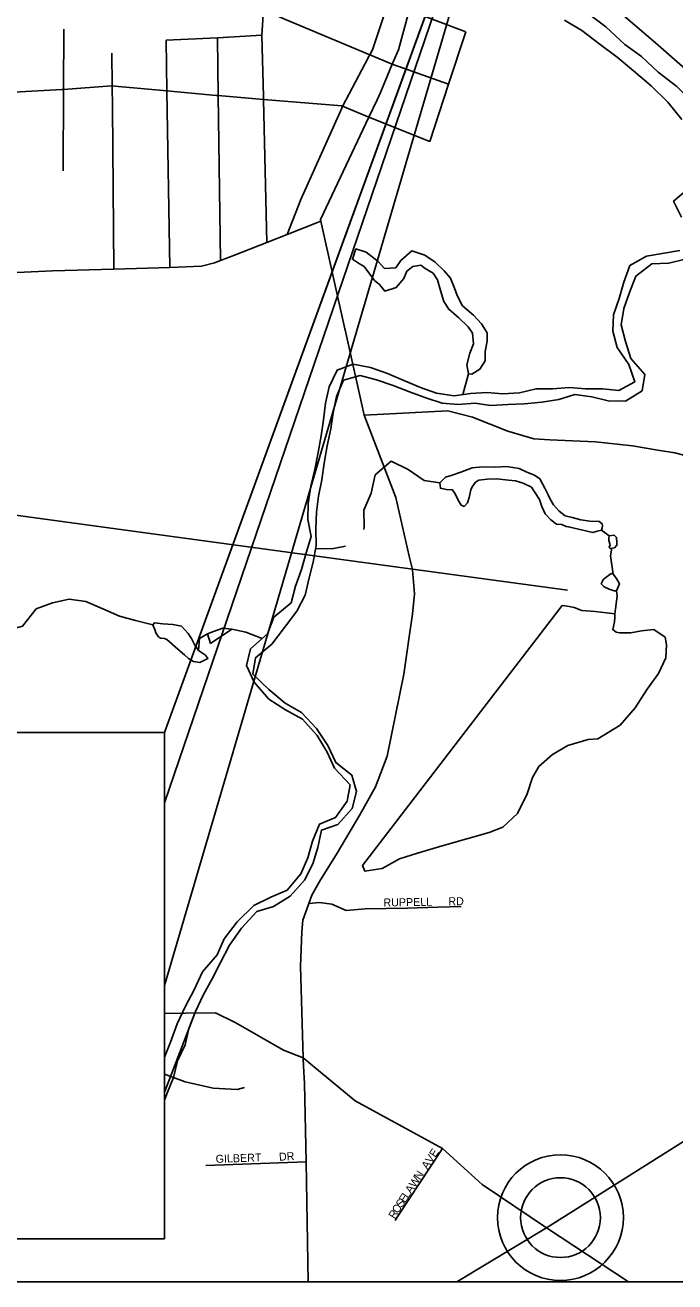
# Model space of a CAD drawing. Extents: x -37878.7 to -37844.7, y -19791.4 to -19769.4.
# Drawn here: x -37873.196 to -37872.428, y -19777.385 to -19775.898 of the extents above; entities that cross this region are included whole.
import ezdxf

# ---------------------------------------------------------------- set-up
doc = ezdxf.new("R2010")
doc.units = 0
for name, color, linetype in [('Default', 7, 'Continuous'), ('GM_X_City_Street', 7, 'Continuous'), ('GM_X_County_Road', 7, 'Continuous'), ('GM_X_Major_River', 7, 'Continuous'), ('GM_X_Minor_Lake', 7, 'Continuous'), ('GM_X_Minor_River', 7, 'Continuous'), ('GM_X_Rail_Line', 7, 'Continuous'), ('GM_X_State_Route', 7, 'Continuous'), ('GM_X_Township_Subdivision', 7, 'Continuous'), ('GM_X_Township_Subdivision_Text', 7, 'Continuous'), ('GM_X_Unincorporated', 7, 'Continuous'), ('SH_Data', 7, 'Continuous'), ('TX_P_1', 7, 'Continuous')]:
    doc.layers.add(name, color=color, linetype=linetype)

msp = doc.modelspace()

# ---------------------------------------------------------------- linework, layer by layer
at = {"layer": 'Default'}
msp.add_line((-37872.5631, -19777.3094), (-37872.5631, -19777.3094), dxfattribs=at)
msp.add_lwpolyline([(-37873.0316, -19777.1396), (-37873.0072, -19777.1485), (-37872.9741, -19777.156), (-37872.9456, -19777.1576), (-37872.9369, -19777.1555)], dxfattribs=at)
at = {"layer": 'GM_X_City_Street'}
for points in [[(-37872.9146, -19775.9827), (-37872.9163, -19775.9098), (-37872.9145, -19775.8801), (-37872.9178, -19775.8408)], [(-37872.9145, -19775.8801), (-37872.8882, -19775.8912), (-37872.7887, -19775.9332), (-37872.7621, -19775.9444)], [(-37872.7907, -19775.9368), (-37872.7905, -19775.9365), (-37872.7887, -19775.9332), (-37872.7856, -19775.9272), (-37872.7678, -19775.8739)], [(-37872.7419, -19775.8807), (-37872.6749, -19775.9059)], [(-37873.1514, -19776.0706), (-37873.1509, -19775.9741), (-37873.1506, -19775.9028)], [(-37873.0295, -19775.916), (-37872.9689, -19775.9129), (-37872.9163, -19775.9098)], [(-37872.7177, -19776.0358), (-37872.6954, -19775.9679), (-37872.6749, -19775.9059)], [(-37873.0253, -19776.1847), (-37873.0286, -19775.9759), (-37873.0295, -19775.916)], [(-37872.9652, -19776.1767), (-37872.968, -19775.9815), (-37872.9689, -19775.9129)], [(-37873.0932, -19775.9952), (-37873.0932, -19775.9952), (-37873.0934, -19775.9698), (-37873.0937, -19775.9314)], [(-37872.8219, -19775.9962), (-37872.8218, -19775.996), (-37872.8208, -19775.9939), (-37872.8206, -19775.9934), (-37872.7907, -19775.9368)], [(-37872.7621, -19775.9444), (-37872.6954, -19775.9679)], [(-37873.5126, -19775.9884), (-37873.5125, -19775.9884), (-37873.4035, -19775.9852), (-37873.35, -19775.9836), (-37873.2955, -19775.982), (-37873.1528, -19775.9743), (-37873.1509, -19775.9741), (-37873.0942, -19775.9697), (-37873.0934, -19775.9698), (-37873.0862, -19775.9705), (-37873.086, -19775.9705)], [(-37873.086, -19775.9705), (-37873.0286, -19775.9759), (-37872.9705, -19775.9813), (-37872.968, -19775.9815), (-37872.9145, -19775.9859), (-37872.8217, -19775.9935), (-37872.8208, -19775.9939), (-37872.7898, -19776.0068)], [(-37872.9106, -19776.1552), (-37872.9145, -19775.9859), (-37872.9146, -19775.9828), (-37872.9146, -19775.9827)], [(-37873.0916, -19776.1867), (-37873.0932, -19775.9952)], [(-37872.8864, -19776.1457), (-37872.8702, -19776.1043), (-37872.8219, -19775.9962)], [(-37872.7898, -19776.0068), (-37872.7177, -19776.0358)], [(-37873.2057, -19776.1908), (-37873.1641, -19776.1888), (-37873.0916, -19776.1867), (-37873.0645, -19776.1859), (-37873.0253, -19776.1847), (-37872.9879, -19776.1835), (-37872.9722, -19776.1795), (-37872.9652, -19776.1767), (-37872.9487, -19776.1701), (-37872.9106, -19776.1552), (-37872.8864, -19776.1457), (-37872.8466, -19776.1301)], [(-37872.7954, -19776.3597), (-37872.6965, -19776.3546), (-37872.667, -19776.3622), (-37872.6255, -19776.3785), (-37872.5948, -19776.3876), (-37872.5758, -19776.3887), (-37872.5218, -19776.3912), (-37872.478, -19776.396), (-37872.448, -19776.401), (-37872.4479, -19776.401)], [(-37872.4479, -19776.401), (-37872.4277, -19776.4043), (-37872.3836, -19776.4156), (-37872.3413, -19776.4212), (-37872.2895, -19776.4275), (-37872.2126, -19776.4447), (-37872.1816, -19776.4523), (-37872.1611, -19776.4625), (-37872.1401, -19776.4772), (-37872.122, -19776.4944), (-37872.1061, -19776.518)]]:
    msp.add_lwpolyline(points, dxfattribs=at)
at = {"layer": 'GM_X_County_Road'}
for points in [[(-37872.6858, -19777.3854), (-37872.5796, -19777.3214), (-37872.0827, -19777.0084)], [(-37872.8675, -19777.1204), (-37872.8909, -19777.111), (-37872.9471, -19777.079), (-37872.9713, -19777.0671), (-37873.0065, -19777.0675), (-37873.0316, -19777.0677)], [(-37872.4825, -19777.3854), (-37872.5796, -19777.3214), (-37872.6559, -19777.2703), (-37872.7025, -19777.2277), (-37872.8058, -19777.171), (-37872.8675, -19777.1204)]]:
    msp.add_lwpolyline(points, dxfattribs=at)
at = {"layer": 'GM_X_Major_River'}
msp.add_line((-37873.0316, -19777.1609), (-37872.9949, -19777.0654), dxfattribs=at)
for points in [[(-37872.4195, -19776.0097), (-37872.4362, -19775.9892), (-37872.4559, -19775.9699), (-37872.4768, -19775.9521), (-37872.496, -19775.9358), (-37872.5176, -19775.9196), (-37872.538, -19775.9045), (-37872.5583, -19775.892)], [(-37872.5285, -19775.886), (-37872.5093, -19775.9001), (-37872.4869, -19775.9208), (-37872.4673, -19775.9352), (-37872.4476, -19775.9538), (-37872.4256, -19775.9708), (-37872.4062, -19775.9905), (-37872.3865, -19776.0098), (-37872.3668, -19776.0287), (-37872.3475, -19776.0469), (-37872.3271, -19776.0597), (-37872.3068, -19776.0741), (-37872.2852, -19776.0888), (-37872.266, -19776.1017), (-37872.2465, -19776.113), (-37872.2254, -19776.1251), (-37872.2062, -19776.1369), (-37872.1839, -19776.15), (-37872.165, -19776.169), (-37872.1449, -19776.186), (-37872.1246, -19776.1989), (-37872.105, -19776.2102), (-37872.0832, -19776.2208)], [(-37872.4201, -19776.1255), (-37872.4292, -19776.1063), (-37872.4095, -19776.09)], [(-37872.4156, -19776.1751), (-37872.4349, -19776.1797), (-37872.4549, -19776.1805), (-37872.4739, -19776.1953), (-37872.4815, -19776.2145), (-37872.4883, -19776.2336), (-37872.4913, -19776.2526), (-37872.486, -19776.2726), (-37872.4799, -19776.2926), (-37872.4632, -19776.3116), (-37872.4666, -19776.3307), (-37872.486, -19776.3429), (-37872.5065, -19776.3425), (-37872.5259, -19776.338), (-37872.546, -19776.335), (-37872.5652, -19776.3411), (-37872.5852, -19776.3442), (-37872.606, -19776.3462), (-37872.6253, -19776.347), (-37872.6454, -19776.3482), (-37872.6644, -19776.3455), (-37872.6837, -19776.3471), (-37872.703, -19776.3456), (-37872.7225, -19776.3392), (-37872.7416, -19776.332), (-37872.761, -19776.3244), (-37872.7809, -19776.318), (-37872.7999, -19776.3128), (-37872.8199, -19776.3181), (-37872.8282, -19776.3377), (-37872.832, -19776.3567), (-37872.8346, -19776.3757), (-37872.8391, -19776.396), (-37872.8425, -19776.4165), (-37872.8455, -19776.4363), (-37872.8492, -19776.4554), (-37872.8519, -19776.4744), (-37872.8526, -19776.4942), (-37872.8522, -19776.5139), (-37872.8556, -19776.5337), (-37872.8608, -19776.5536), (-37872.8653, -19776.5726), (-37872.8748, -19776.5918), (-37872.8895, -19776.6111), (-37872.9047, -19776.6308), (-37872.9237, -19776.6468), (-37872.927, -19776.6662), (-37872.9081, -19776.6844), (-37872.8888, -19776.7007), (-37872.8696, -19776.7116), (-37872.8518, -19776.7306), (-37872.8385, -19776.7505), (-37872.829, -19776.7708), (-37872.8098, -19776.7859), (-37872.8044, -19776.8051), (-37872.8097, -19776.825), (-37872.8264, -19776.844), (-37872.8459, -19776.8508), (-37872.85, -19776.8714), (-37872.8561, -19776.8905), (-37872.8659, -19776.9101), (-37872.8829, -19776.9291), (-37872.9027, -19776.9412), (-37872.9223, -19776.947), (-37872.9405, -19776.9667), (-37872.9548, -19776.9868), (-37872.9654, -19777.0075), (-37872.9752, -19777.0267), (-37872.9858, -19777.0459), (-37872.9949, -19777.0654)], [(-37872.9082, -19776.6958), (-37872.9253, -19776.6756), (-37872.9344, -19776.6561), (-37872.9296, -19776.6363), (-37872.9095, -19776.6184), (-37872.9023, -19776.5989), (-37872.8818, -19776.5817), (-37872.8766, -19776.5622), (-37872.8694, -19776.5424), (-37872.8641, -19776.5225), (-37872.8581, -19776.5034), (-37872.8619, -19776.483), (-37872.8616, -19776.464), (-37872.8586, -19776.4438), (-37872.8537, -19776.424), (-37872.8496, -19776.4038), (-37872.8462, -19776.3843), (-37872.8435, -19776.3653), (-37872.8409, -19776.3455), (-37872.8368, -19776.3261), (-37872.8273, -19776.3065), (-37872.8082, -19776.2993), (-37872.788, -19776.3034), (-37872.7678, -19776.3105), (-37872.7483, -19776.3185), (-37872.7288, -19776.3268), (-37872.7097, -19776.3336), (-37872.6888, -19776.3366), (-37872.6696, -19776.3339), (-37872.6503, -19776.3327), (-37872.6313, -19776.3346), (-37872.6116, -19776.3334), (-37872.592, -19776.3284), (-37872.5727, -19776.3284), (-37872.5523, -19776.3268), (-37872.5333, -19776.3283), (-37872.5132, -19776.3283), (-37872.4942, -19776.3305), (-37872.4751, -19776.3202), (-37872.4824, -19776.2995), (-37872.496, -19776.2797), (-37872.501, -19776.2604), (-37872.5003, -19776.2411), (-37872.4938, -19776.2216), (-37872.4882, -19776.2021), (-37872.481, -19776.1826), (-37872.4612, -19776.1715), (-37872.4219, -19776.1646)], [(-37873.0316, -19777.1193), (-37873.0244, -19777.1017), (-37873.0165, -19777.0799), (-37873.0067, -19777.0592), (-37872.9965, -19777.0397), (-37872.9864, -19777.0186), (-37872.9694, -19776.9985), (-37872.9611, -19776.9793), (-37872.9456, -19776.9592), (-37872.9259, -19776.9398), (-37872.9056, -19776.9303), (-37872.8865, -19776.9219), (-37872.8702, -19776.9026), (-37872.8619, -19776.8834), (-37872.8566, -19776.864), (-37872.8483, -19776.8437), (-37872.8292, -19776.836), (-37872.8156, -19776.8164), (-37872.8118, -19776.7973), (-37872.8304, -19776.7776), (-37872.8391, -19776.7584), (-37872.8509, -19776.7386), (-37872.8683, -19776.7196), (-37872.8883, -19776.7083), (-37872.9082, -19776.6958)], [(-37873.0316, -19777.1193), (-37873.0244, -19777.1017), (-37873.0165, -19777.0799), (-37873.0067, -19777.0592), (-37872.9965, -19777.0397), (-37872.9864, -19777.0186), (-37872.9694, -19776.9985), (-37872.9611, -19776.9793), (-37872.9456, -19776.9592), (-37872.9259, -19776.9398), (-37872.9056, -19776.9303), (-37872.8865, -19776.9219), (-37872.8702, -19776.9026), (-37872.8619, -19776.8834), (-37872.8566, -19776.864), (-37872.8483, -19776.8437), (-37872.8292, -19776.836), (-37872.8156, -19776.8164), (-37872.8118, -19776.7973), (-37872.8304, -19776.7776), (-37872.8391, -19776.7584), (-37872.8509, -19776.7386), (-37872.8683, -19776.7196), (-37872.8883, -19776.7083), (-37872.9082, -19776.6958)], [(-37872.9949, -19777.0654), (-37873.0028, -19777.0857), (-37873.0069, -19777.1048), (-37873.016, -19777.124), (-37873.0209, -19777.1434), (-37873.0288, -19777.163), (-37873.0316, -19777.1703)]]:
    msp.add_lwpolyline(points, dxfattribs=at)
at = {"layer": 'GM_X_Minor_Lake'}
for p, q in [((-37872.7954, -19776.1836), (-37872.783, -19776.2004)), ((-37872.5537, -19776.492), (-37872.5248, -19776.4986)), ((-37872.5057, -19776.508), (-37872.5044, -19776.5133)), ((-37872.5033, -19776.5471), (-37872.5127, -19776.5541)), ((-37872.5609, -19776.5851), (-37872.7973, -19776.8927)), ((-37872.9807, -19776.6184), (-37872.9771, -19776.6297)), ((-37873.0287, -19776.6251), (-37873.0156, -19776.6366))]:
    msp.add_line(p, q, dxfattribs=at)
for points in [[(-37872.783, -19776.2004), (-37872.7772, -19776.2052), (-37872.771, -19776.2127), (-37872.7574, -19776.2086), (-37872.7485, -19776.1978), (-37872.7449, -19776.1894), (-37872.7378, -19776.1839), (-37872.7284, -19776.1822), (-37872.723, -19776.1859), (-37872.7138, -19776.1914), (-37872.7087, -19776.1996), (-37872.7051, -19776.212), (-37872.701, -19776.2252), (-37872.6951, -19776.2342), (-37872.6832, -19776.2446), (-37872.6723, -19776.255), (-37872.6673, -19776.2625), (-37872.6658, -19776.2753), (-37872.6702, -19776.2861), (-37872.674, -19776.3002), (-37872.6719, -19776.3108), (-37872.6678, -19776.3111), (-37872.6584, -19776.3052), (-37872.6522, -19776.2952), (-37872.652, -19776.2842), (-37872.65, -19776.272), (-37872.6498, -19776.2621), (-37872.6565, -19776.2516), (-37872.6658, -19776.2412), (-37872.6789, -19776.2301), (-37872.6852, -19776.2181), (-37872.6884, -19776.2094), (-37872.6932, -19776.1974), (-37872.7006, -19776.1888), (-37872.7114, -19776.1784), (-37872.7234, -19776.1703), (-37872.739, -19776.1653), (-37872.752, -19776.1766), (-37872.7579, -19776.1851), (-37872.7711, -19776.1861), (-37872.7789, -19776.1779), (-37872.7931, -19776.1669), (-37872.805, -19776.1629), (-37872.8093, -19776.1752), (-37872.8008, -19776.1807), (-37872.7954, -19776.1836)], [(-37872.5248, -19776.4986), (-37872.5195, -19776.4969), (-37872.5146, -19776.4957), (-37872.5139, -19776.493), (-37872.5132, -19776.4907), (-37872.5137, -19776.4884), (-37872.5175, -19776.4855), (-37872.5285, -19776.485), (-37872.5391, -19776.4837), (-37872.5494, -19776.4809), (-37872.5574, -19776.4788), (-37872.5647, -19776.4732), (-37872.5713, -19776.4658), (-37872.5753, -19776.459), (-37872.5776, -19776.4538), (-37872.5816, -19776.4462), (-37872.5875, -19776.435), (-37872.5937, -19776.4306), (-37872.6028, -19776.427), (-37872.612, -19776.4226), (-37872.6268, -19776.4203), (-37872.6401, -19776.4213), (-37872.6552, -19776.4209), (-37872.6677, -19776.4219), (-37872.6809, -19776.4271), (-37872.6925, -19776.4312), (-37872.6993, -19776.4332), (-37872.706, -19776.4398), (-37872.7051, -19776.4462), (-37872.6963, -19776.4479), (-37872.6914, -19776.4478), (-37872.6875, -19776.4527), (-37872.684, -19776.4602), (-37872.6804, -19776.4662), (-37872.677, -19776.4676), (-37872.6729, -19776.4634), (-37872.6711, -19776.4569), (-37872.6691, -19776.4481), (-37872.6676, -19776.4443), (-37872.6636, -19776.4389), (-37872.6595, -19776.4365), (-37872.65, -19776.4352), (-37872.6383, -19776.4349), (-37872.6246, -19776.4365), (-37872.6162, -19776.4375), (-37872.6071, -19776.44), (-37872.5975, -19776.4447), (-37872.594, -19776.4503), (-37872.5881, -19776.4593), (-37872.5853, -19776.4676), (-37872.5813, -19776.4766), (-37872.5744, -19776.4837), (-37872.5678, -19776.4885), (-37872.5614, -19776.4891), (-37872.5564, -19776.4913), (-37872.5537, -19776.492)], [(-37872.5044, -19776.5133), (-37872.5055, -19776.516), (-37872.5043, -19776.5175), (-37872.499, -19776.5166), (-37872.4965, -19776.5135), (-37872.4965, -19776.5105), (-37872.4967, -19776.5044), (-37872.4994, -19776.5018), (-37872.5054, -19776.5023), (-37872.5057, -19776.505), (-37872.5057, -19776.508)], [(-37872.5127, -19776.5541), (-37872.5134, -19776.556), (-37872.5148, -19776.5591), (-37872.5113, -19776.5628), (-37872.5056, -19776.5657), (-37872.4995, -19776.5675), (-37872.4969, -19776.5674), (-37872.4932, -19776.5594), (-37872.4968, -19776.553), (-37872.5007, -19776.5478), (-37872.5033, -19776.5471)], [(-37872.7973, -19776.8927), (-37872.7945, -19776.8995), (-37872.7741, -19776.896), (-37872.7535, -19776.8849), (-37872.7321, -19776.878), (-37872.7031, -19776.8694), (-37872.6737, -19776.8612), (-37872.6474, -19776.8534), (-37872.6312, -19776.8474), (-37872.6141, -19776.8311), (-37872.6025, -19776.8077), (-37872.596, -19776.7886), (-37872.5887, -19776.7755), (-37872.5724, -19776.7611), (-37872.5544, -19776.7505), (-37872.5303, -19776.7435), (-37872.519, -19776.7429), (-37872.4924, -19776.7264), (-37872.4746, -19776.7059), (-37872.4607, -19776.6839), (-37872.4471, -19776.6654), (-37872.4384, -19776.647), (-37872.4376, -19776.6314), (-37872.4393, -19776.6224), (-37872.4527, -19776.6135), (-37872.4674, -19776.615), (-37872.4799, -19776.6172), (-37872.4932, -19776.6174), (-37872.4973, -19776.6164), (-37872.5012, -19776.6134), (-37872.4991, -19776.6043), (-37872.4988, -19776.5993), (-37872.4986, -19776.5948), (-37872.5088, -19776.5935), (-37872.5221, -19776.5919), (-37872.5377, -19776.5907), (-37872.5468, -19776.5871), (-37872.5548, -19776.5857), (-37872.5609, -19776.5851)], [(-37873.0156, -19776.6366), (-37873.0078, -19776.6432), (-37873.0032, -19776.6477), (-37872.9971, -19776.651), (-37872.9898, -19776.6523), (-37872.9801, -19776.6476), (-37872.9832, -19776.6435), (-37872.9913, -19776.6383), (-37872.996, -19776.6312), (-37872.9995, -19776.6241), (-37873.0034, -19776.6181), (-37873.0116, -19776.6095), (-37873.0215, -19776.6075), (-37873.0336, -19776.6066), (-37873.0435, -19776.6053), (-37873.0453, -19776.6076), (-37873.0425, -19776.6144), (-37873.0417, -19776.6174), (-37873.0386, -19776.6219), (-37873.0363, -19776.6234), (-37873.0317, -19776.624), (-37873.0287, -19776.6251)], [(-37872.9771, -19776.6297), (-37872.952, -19776.6128), (-37872.9626, -19776.6119), (-37872.9736, -19776.6156), (-37872.9807, -19776.6184)]]:
    msp.add_lwpolyline(points, dxfattribs=at)
at = {"layer": 'GM_X_Minor_River'}
for points in [[(-37872.6787, -19776.3352), (-37872.6719, -19776.3108)], [(-37872.706, -19776.4398), (-37872.7242, -19776.4371), (-37872.7434, -19776.4239), (-37872.7633, -19776.4141), (-37872.7823, -19776.4304), (-37872.7872, -19776.4518), (-37872.7958, -19776.4721), (-37872.7954, -19776.4918), (-37872.7958, -19776.4949)], [(-37872.5054, -19776.5023), (-37872.5146, -19776.4957)], [(-37872.8528, -19776.5177), (-37872.8317, -19776.5173), (-37872.8173, -19776.5147)], [(-37872.5007, -19776.5478), (-37872.5038, -19776.5262), (-37872.5025, -19776.5172)], [(-37873.0453, -19776.6076), (-37873.0659, -19776.6027), (-37873.0849, -19776.5974), (-37873.1044, -19776.5888), (-37873.1247, -19776.5801), (-37873.1445, -19776.5775), (-37873.1641, -19776.5817), (-37873.1832, -19776.5889), (-37873.1995, -19776.6094), (-37873.2217, -19776.6152), (-37873.2412, -19776.6232), (-37873.2539, -19776.6287)], [(-37872.4986, -19776.5948), (-37872.496, -19776.5739), (-37872.4969, -19776.5674)], [(-37872.9807, -19776.6184), (-37872.9903, -19776.6239), (-37872.9913, -19776.6383)], [(-37872.9158, -19776.6238), (-37872.9353, -19776.6163), (-37872.952, -19776.6128)]]:
    msp.add_lwpolyline(points, dxfattribs=at)
at = {"layer": 'GM_X_Rail_Line'}
for points in [[(-37872.4995, -19775.8773), (-37872.4508, -19775.9191), (-37872.3961, -19775.9668), (-37872.3508, -19776.0064), (-37872.336, -19776.0187), (-37872.3223, -19776.0296), (-37872.3079, -19776.0402), (-37872.296, -19776.0482), (-37872.2802, -19776.0586), (-37872.2637, -19776.0691), (-37872.2552, -19776.0744)], [(-37872.5548, -19776.5667), (-37872.7322, -19776.5426), (-37872.8542, -19776.5262), (-37873.063, -19776.4978), (-37873.3325, -19776.4609), (-37873.8193, -19776.3953), (-37874.1091, -19776.3564), (-37874.7711, -19776.2673)]]:
    msp.add_lwpolyline(points, dxfattribs=at)
at = {"layer": 'GM_X_State_Route'}
for points in [[(-37872.7606, -19775.9408), (-37872.7549, -19775.9273), (-37872.7419, -19775.8807), (-37872.7316, -19775.8432), (-37872.7249, -19775.7914), (-37872.7243, -19775.7657), (-37872.7241, -19775.7571)], [(-37872.7801, -19775.9864), (-37872.7761, -19775.9779), (-37872.7621, -19775.9444), (-37872.7606, -19775.9408)], [(-37872.818, -19776.2586), (-37872.8182, -19776.2576), (-37872.8466, -19776.1301), (-37872.8471, -19776.1281), (-37872.7898, -19776.0068), (-37872.7801, -19775.9864)], [(-37872.7386, -19776.5407), (-37872.7422, -19776.5264), (-37872.758, -19776.4571), (-37872.7954, -19776.3597), (-37872.818, -19776.2586)], [(-37872.867, -19777.1301), (-37872.8675, -19777.1204), (-37872.8706, -19777.0119), (-37872.869, -19776.9711), (-37872.868, -19776.9574), (-37872.8609, -19776.9375), (-37872.8573, -19776.9278), (-37872.8471, -19776.9095), (-37872.8283, -19776.88), (-37872.8003, -19776.8326), (-37872.7819, -19776.7995), (-37872.7682, -19776.7633), (-37872.7483, -19776.666), (-37872.7412, -19776.6166), (-37872.7381, -19776.5952), (-37872.7356, -19776.5712), (-37872.7381, -19776.5427), (-37872.7386, -19776.5407)], [(-37872.8617, -19777.3854), (-37872.864, -19777.2434), (-37872.866, -19777.1505), (-37872.867, -19777.1301)]]:
    msp.add_lwpolyline(points, dxfattribs=at)
at = {"layer": 'GM_X_Township_Subdivision'}
for points in [[(-37872.8609, -19776.9375), (-37872.8481, -19776.9365), (-37872.8334, -19776.9385), (-37872.8168, -19776.9458), (-37872.7941, -19776.9441), (-37872.7442, -19776.9431), (-37872.7081, -19776.9421), (-37872.6805, -19776.9411)], [(-37872.7585, -19777.3129), (-37872.757, -19777.3101), (-37872.7025, -19777.2277)], [(-37872.9827, -19777.2475), (-37872.864, -19777.2434)]]:
    msp.add_lwpolyline(points, dxfattribs=at)
at = {"layer": 'GM_X_Unincorporated'}
for radius in [0.0744, 0.0472]:
    msp.add_circle((-37872.5631, -19777.3094), radius, dxfattribs=at)
at = {"layer": 'SH_Data'}
msp.add_line((-37876.1504, -19777.3854), (-37869.1504, -19777.3854), dxfattribs=at)
at = {"layer": 'TX_P_1'}
for p, q in [((-37873.0316, -19776.8184), (-37872.5773, -19775.4866)), ((-37872.5773, -19775.4866), (-37873.0316, -19776.7352)), ((-37874.7897, -19776.7352), (-37873.0316, -19776.7352)), ((-37873.0316, -19776.7352), (-37873.0316, -19777.3343)), ((-37873.0316, -19777.3343), (-37874.7897, -19777.3343))]:
    msp.add_line(p, q, dxfattribs=at)
msp.add_lwpolyline([(-37873.0316, -19776.7352), (-37872.5773, -19775.4866), (-37873.0316, -19777.0347)], close=True, dxfattribs=at)

# ---------------------------------------------------------------- texts
at = {"layer": 'GM_X_Township_Subdivision_Text'}
for s, rotation, p in [('RUPPELL', 0.9544, (-37872.7725, -19776.9412)), ('RD', 0, (-37872.6958, -19776.9396)), ('GILBERT', 1.9422, (-37872.9709, -19777.2446)), ('DR', 3.011, (-37872.8959, -19777.2421)), ('AVE', 56.3099, (-37872.7206, -19777.2529)), ('W', 56.7294, (-37872.7352, -19777.2746)), ('N', 56.7282, (-37872.7293, -19777.2655)), ('A', 56.7356, (-37872.7398, -19777.2815)), ('O', 56.8373, (-37872.7553, -19777.3052)), ('S', 56.719, (-37872.7508, -19777.2983)), ('E', 56.744, (-37872.7471, -19777.2927)), ('L', 56.719, (-37872.7434, -19777.2871)), ('R', 58.4864, (-37872.7592, -19777.3116))]:
    msp.add_text(s, height=0.00947, rotation=rotation, dxfattribs=at).set_placement(p)

doc.saveas('drawing.dxf')
